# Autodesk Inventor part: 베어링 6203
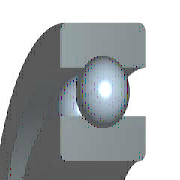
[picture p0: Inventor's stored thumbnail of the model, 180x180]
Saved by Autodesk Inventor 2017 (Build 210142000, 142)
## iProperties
Created: 2012-02
Part Number: 베어링 6203
Material: 강철, 연강
Description: 깊은 그루브 볼 베어링
Document SubType Name: Modeling
Standard: KS B 2023
Designer: mduedu
Standards Organization: KS
Language: ko-KR
Size Designation: 6203 - 17 x 40 x 12
Categories: <MemberInstance><Categories><Category DisplayName="샤프트 부품" InternalName="7f7aeb1f-a693-4053-b835-cee3144e0d98" Mnemonic="SHFT"><Category DisplayName="베어링" Inter
Density: 7.85 g/cm^3
Appearance: 노란색
Mass: 64.8982 g
Surface Area: 64.3582 cm^2
Volume: 8.26729 cm^3
IsCustomPart: 1
Author: mduedu
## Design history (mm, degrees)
sketch "스케치" dims "d0" = 5.98 (= -0.26 x WD + 0.26 x BD)
  geometry: L1 (3.01, 14.25)-(8.99, 14.25); L2 (6, 14.25)-(6, 11.26); L3 (6, 14.25)-(6, 17.24); L4 (3.778, 12.249)-(0, 12.249); L5 (0, 8.5)-(12, 8.5); L6 (3.778, 16.251)-(0, 16.251); L7 (0, 20)-(12, 20); L8 (12, 8.5)-(12, 12.249); L9 (8.222, 12.249)-(12, 12.249); L10 (8.222, 16.251)-(12, 16.251); L11 (12, 20)-(12, 16.251); L12 (-1.4, 0)-(8.4, 0) reference; L13 (0, -0.3)-(0, 5.3) reference
  constraints: 22 end point, 4 point on line, 2 collinear, 2 perpendicular, 2 symmetric about line, 1 midpoint, 1 parallel, 14 other
  dimensions: "d9" = 17 diameter of L5 L12 (= WD); "d11" = 40 diameter of L7 L12 (= BD); "d12" = 12 distance between parallel lines of L8 L13 (= KB); "d13" = 24.498 diameter of L9 L12 (= 0.326 x BD + 0.674 x WD)
revolve "본체" stored, may be unused: angle "d6" = 90 deg
revolve "볼" stored, may be unused: angle "d7" = 90 deg
pattern_circular "IDS_ARRAYBALL[SIMPL:T]" dims angle "d3" = 360 deg
body "Solid1"
fillet "모깎기1" dims "d1" = 0.6 (= KRS)
other parameters: "WD" = 17 [user parameter; used in 5 equation terms], "BD" = 40 [user parameter; used in 5 equation terms], "KB" = 12 [user parameter; used in 1 equation term], "KRS" = 0.6 [user parameter; used in 1 equation term], "d4" = 0, "d5" = 0, "d8" = 0, "d14" = 0, "d15" = 0, "BBA" = 0 [user parameter], "BC0" = 4750000 [user parameter], "BC" = 9560000 [user parameter], "WR" = 8.5 (= 0.5 x WD) [user parameter]
